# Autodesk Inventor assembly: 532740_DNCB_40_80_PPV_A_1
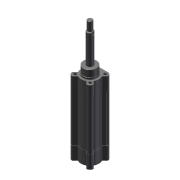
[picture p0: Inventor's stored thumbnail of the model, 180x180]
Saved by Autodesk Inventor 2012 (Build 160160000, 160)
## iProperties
Company: CAD-Verlag
Created: 2004-09
Part Number: 532740_DNCB_40_80_PPV_A_1
Document SubType Name: Assembly
Designer: Greiling
Manufacturer: Standard
Standards Organization: Custom
Checked By: Jürgen Kronas
Stock Number: 10-10012
Author: Juergen Kronas
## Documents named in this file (3)
- C:\Daten Vault 2012 Inventor\Kapitel 6\6.2\Anschlag\532740_DNCB_40_80_PPV_A_1.iam
- C:\Daten Vault 2012 Inventor\Kapitel 6\6.2\Anschlag\1.ipt
- C:\Daten Vault 2012 Inventor\Kapitel 6\6.2\Anschlag\2.ipt
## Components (2 placed, 2 different names)
1. 1 — Passend:1, Abstand
2. 2 — Passend:1, Abstand
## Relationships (2: Mate 1, Flush 1)
- Passend:1 [Mate]: 1 ↔ 2
- Abstand [Flush]: 1 ↔ 2
